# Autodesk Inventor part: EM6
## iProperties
IsCustomPart: 0
Created: 2006-02
Part Number: EM6
Material: Steel, Mild
Description: 六角ナット
Document SubType Name: Modeling
Standard: JIS B 1181
Designer: t-ikumi
Standards Organization: JIS
Language: ja-JP
Size Designation: 等級 3 仕上程度 並 M6
Categories: <MemberInstance><Categories><Category DisplayName="締結器具" InternalName="e4da775c-781d-43d5-af7c-5136215cf5a6" Mnemonic="FSTN"><Category DisplayName="ナット" Interna
Author: t-ikumi
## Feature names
1. ボディ [Extrusion]
2. 面取り1 [Revolution]
3. ねじ [Hole]
4. 面取り2 [Chamfer]
5. 面取り3 [Chamfer]
